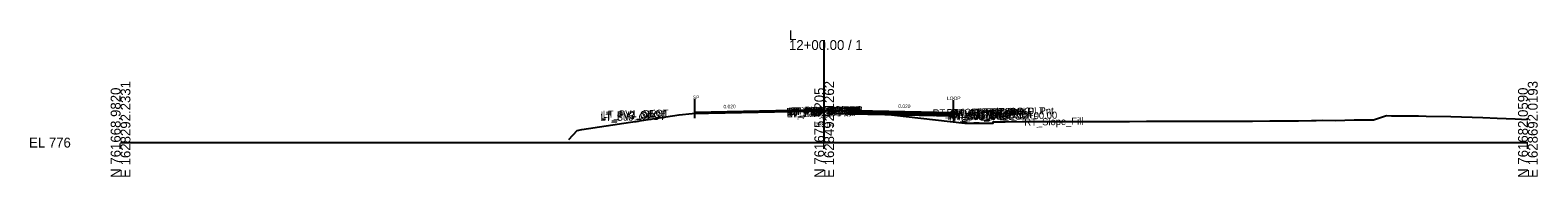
# Model space of a CAD drawing. Extents: x -26 to 4403, y -510 to 9556.
# Drawn here: x -25.7 to 402.8, y 1990.3 to 2031.9 of the extents above; entities that cross this region are included whole.
import ezdxf

# ---------------------------------------------------------------- set-up
doc = ezdxf.new("R2010")
doc.units = 0
for name, color, linetype in [('Default', 7, 'Continuous'), ('Exist CMT Pavement', 7, 'Continuous'), ('Exist Cross Section Cell', 7, 'Continuous'), ('Exist XS Center Line Elevation Label', 7, 'Continuous'), ('Exist XS Ground Line', 7, 'Continuous'), ('Prop CMT Pvmt Course 1', 7, 'Continuous'), ('Prop CMT Pvmt Course 2', 7, 'Continuous'), ('Prop CMT Pvmt Course 3', 7, 'Continuous'), ('Prop CMT Pvmt Surface', 7, 'Continuous'), ('Prop CMT Shear Line', 7, 'Continuous'), ('Prop CMT Subgrade Earthwork', 7, 'Continuous'), ('Prop XS Hydro Elevations', 7, 'Continuous'), ('Prop XS SE Text', 7, 'Continuous'), ('Scratch_Level_0', 7, 'Continuous')]:
    doc.layers.add(name, color=color, linetype=linetype)

msp = doc.modelspace()

# ---------------------------------------------------------------- linework, layer by layer
at = {"layer": 'Exist CMT Pavement'}
msp.add_lwpolyline([(163.25, 2008.31), (200, 2009.04), (207.5, 2009.19)], dxfattribs=at)
at = {"layer": 'Exist Cross Section Cell'}
for p, q in [((200, 2000), (200, 2029.08)), ((0, 2000), (200, 2000)), ((200, 2000), (400, 2000))]:
    msp.add_line(p, q, dxfattribs=at)
at = {"layer": 'Exist XS Ground Line'}
msp.add_lwpolyline([(127.44, 2000.93), (129.77, 2003.47), (131.12, 2003.73), (158.76, 2007.86), (162.5, 2008.29), (200, 2009.04), (207.5, 2009.19), (239.98, 2005.53), (241.07, 2005.5), (241.39, 2005.49), (246.44, 2005.55), (247.25, 2005.52), (248.04, 2005.5), (248.04, 2005.94), (249.96, 2005.94), (251.43, 2005.94), (256.23, 2005.96), (261.47, 2005.97), (266.43, 2005.98), (271.51, 2005.99), (276.7, 2006.01), (281.54, 2006.02), (286.73, 2006.03), (291.58, 2006.04), (296.62, 2006.06), (301.62, 2006.07), (305.8, 2006.08), (309.98, 2006.09), (310.86, 2006.08), (311.66, 2006.08), (316.69, 2006.06), (321.7, 2006.06), (326.69, 2006.2), (331.74, 2006.19), (334.83, 2006.18), (338.48, 2006.29), (339.81, 2006.29), (341.5, 2006.34), (345.32, 2006.32), (350.67, 2006.48), (356.12, 2006.5), (359.83, 2007.66), (361.2, 2007.64), (368.96, 2007.57), (371.06, 2007.53), (378.1, 2007.39), (381.12, 2007.29), (387.23, 2007.1), (391.24, 2006.93), (396.38, 2006.7), (400, 2006.52)], dxfattribs=at)
at = {"layer": 'Prop CMT Pvmt Course 1'}
for points in [[(200, 2009.27), (163.25, 2008.54)], [(200, 2009.27), (236.75, 2008.54)], [(236.75, 2008.29), (207.5, 2008.87)]]:
    msp.add_lwpolyline(points, dxfattribs=at)
at = {"layer": 'Prop CMT Pvmt Course 2'}
for points in [[(207.5, 2008.87), (236.75, 2008.29)], [(236.75, 2007.95), (207.5, 2008.54)]]:
    msp.add_lwpolyline(points, dxfattribs=at)
at = {"layer": 'Prop CMT Pvmt Course 3'}
for points in [[(207.5, 2008.54), (236.75, 2007.95)], [(236.75, 2007.62), (207.5, 2008.21)]]:
    msp.add_lwpolyline(points, dxfattribs=at)
at = {"layer": 'Prop CMT Pvmt Surface'}
for points in [[(200, 2009.27), (163.25, 2008.54)], [(200, 2009.27), (236.75, 2008.54)]]:
    msp.add_lwpolyline(points, dxfattribs=at)
at = {"layer": 'Prop CMT Shear Line'}
for p, q in [((163.25, 2006.98), (163.25, 2012.29)), ((236.75, 2006.73), (236.75, 2012.01))]:
    msp.add_line(p, q, dxfattribs=at)
at = {"layer": 'Prop CMT Subgrade Earthwork'}
for p, q in [((207.5, 2009.19), (207.5, 2008.21)), ((236.75, 2008.54), (236.75, 2005.89))]:
    msp.add_line(p, q, dxfattribs=at)
msp.add_lwpolyline([(207.5, 2008.21), (236.75, 2007.62)], dxfattribs=at)

# ---------------------------------------------------------------- texts
at = {"layer": 'Default'}
msp.add_text('-', height=0.0001, dxfattribs=at).set_placement((0, 2000))
at = {"layer": 'Exist Cross Section Cell'}
for s, p in [('L', (190, 2029.08)), ('12+00.00 / 1', (190, 2026.28)), ('EL 776', (-26, 1998.6))]:
    msp.add_text(s, height=2.8, dxfattribs=at).set_placement(p)
for s, p in [('N 761668.9820', (0, 1990)), ('E 1628292.2331', (2.8, 1990)), ('N 761675.5205', (200, 1990)), ('E 1628492.1262', (202.8, 1990)), ('N 761682.0590', (400, 1990)), ('E 1628692.0193', (402.8, 1990))]:
    msp.add_text(s, height=2.8, rotation=90, dxfattribs=at).set_placement(p)
at = {"layer": 'Exist XS Center Line Elevation Label'}
msp.add_text('785.04', height=1.2, dxfattribs=at).set_placement((197.46, 2004.44))
at = {"layer": 'Prop XS Hydro Elevations'}
for s, p in [('SP', (162.67, 2012.33)), ('LOOP', (234.91, 2012.06))]:
    msp.add_text(s, height=1, rotation=360, dxfattribs=at).set_placement(p)
at = {"layer": 'Prop XS SE Text'}
for rotation, p in [(1.1452, (171.39, 2009.7)), (358.8545, (221.05, 2009.85))]:
    msp.add_text('0.020', height=1, rotation=rotation, dxfattribs=at).set_placement(p)
at = {"layer": 'Scratch_Level_0'}
for s, p in [('RT_PV2_OEEOP', (189.28, 2007.81)), ('RT_PV3_OEEOP', (189.28, 2007.47)), ('LT_PV2_OEEOP', (189.33, 2007.81)), ('LT_PV3_OEEOP', (189.33, 2007.48)), ('RT_PV1_OEEOP', (189.85, 2007.94)), ('LT_PV1_OEEOP', (189.9, 2007.94)), ('RT_PV2_IEEOP', (189.93, 2007.82)), ('LT_PV2_IEEOP', (189.97, 2007.82)), ('RT_PV1_IEEOP', (190.49, 2007.96)), ('LT_PV1_IEEOP', (190.54, 2007.96)), ('PV2_PGL', (193.93, 2007.9)), ('PV1_PGL', (194.49, 2008.16)), ('RT_Sub_Trench_Out_DLT', (230.85, 2007.4)), ('RT_CG_Top_Face', (234.8, 2007.49)), ('RT_CG_Top_BOC', (236.32, 2007.51)), ('12+00.00', (241.61, 2007.62)), ('12+00.00', (243.08, 2007.64)), ('RT_CSLP_Pnt', (247.71, 2007.73)), ('LT_Sub_OEOT', (136.42, 2006.08)), ('LT_PV2_OEOT', (136.52, 2006.75)), ('LT_PV3_OEOT', (136.52, 2006.42)), ('LT_PV1_OEOT', (137.09, 2007.01)), ('RT_Sub_OEEOP', (189.19, 2007.14)), ('LT_Sub_OEEOP', (189.23, 2007.14)), ('RT_CG1_Shelf_Out', (235.09, 2006.45)), ('RT_CG_Bot_IE', (235.45, 2006.58)), ('RT_Sub_OEOT', (235.61, 2006.24)), ('RT_PV2_OEOT', (235.71, 2006.91)), ('RT_PV3_OEOT', (235.71, 2006.58)), ('RT_CG_Top_Gut', (235.77, 2007.01)), ('RT_PV1_OEOT', (236.27, 2007.18)), ('RT_CG_Bot_BOC', (236.35, 2006.49)), ('RT_Sub_OEOP', (238.98, 2006.18)), ('12+00.00', (239.44, 2007.23)), ('12+00.00', (255.01, 2006.57)), ('RT_Slope_Fill', (256.9, 2004.79))]:
    msp.add_text(s, height=2, rotation=1.1458, dxfattribs=at).set_placement(p)

doc.saveas('drawing.dxf')
